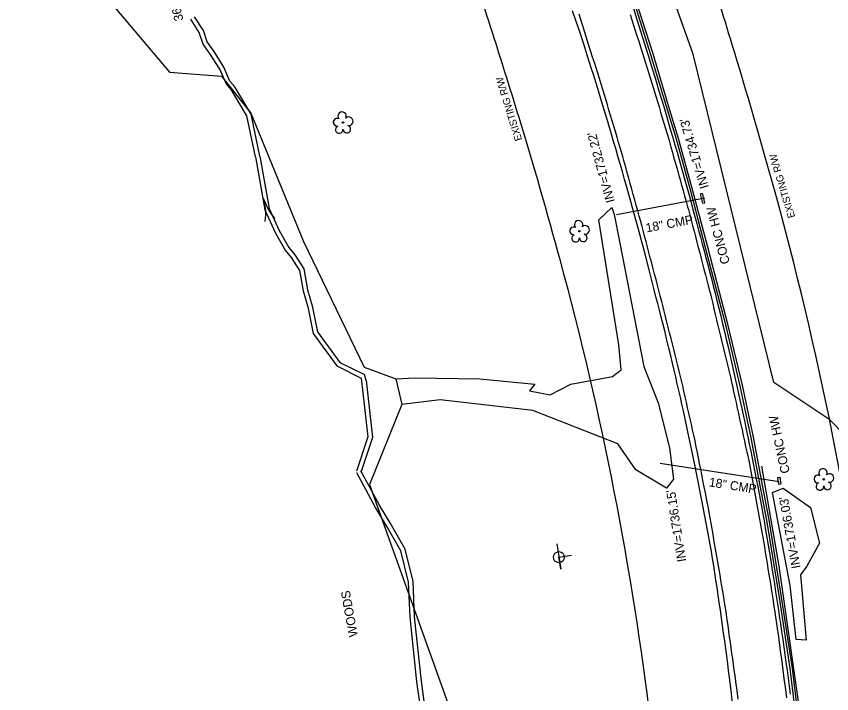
# Model space of a CAD drawing. Extents: x 472260 to 482161, y 489063 to 507124.
# Drawn here: x 481070.1 to 481432.2, y 491569.8 to 491870.7 of the extents above; entities that cross this region are included whole.
import ezdxf

# ---------------------------------------------------------------- set-up
doc = ezdxf.new("R2010")
doc.units = 0
for name, color, linetype in [('Exist Structure Minor Drop Inlet Cogo Elevation', 7, 'Continuous'), ('Exist Structure Minor Pipes CMP 15 Inch Cogo Point CELL', 7, 'Continuous'), ('Exist Structure Minor Pipes CMP 30 Inch', 7, 'Continuous'), ('Prop Drainage Structure Catch Basin Convert From Junction Box Label', 7, 'Continuous'), ('Prop Drainage Structure Drop Inlet Grate 2 Narrow Slots and Sag Grates 840 24 CELL', 7, 'Continuous'), ('Prop Drainage Structure Drop Inlet Grate 2 Wide Slots and Flat Grates 840 20 Label', 7, 'Continuous'), ('Prop Drainage Structure Pipe RCP 24in Class III', 7, 'Continuous'), ('Prop Drainage Structure Pipe RCP 36in Class III', 7, 'Continuous'), ('Prop Drainage Structure Pipe RCP 66in Class III', 7, 'Continuous'), ('Prop Drainage Structure Pipe RCP 66in Class IV', 7, 'Continuous'), ('Prop Drainage Structure Pipe RCP 66in Class IV Label', 7, 'Continuous'), ('Prop Drainage Structure Pipe Stub Out CELL', 7, 'Continuous'), ('Prop Drainage Structure Pipe Welded Steel 72in Label', 7, 'Continuous'), ('Prop Drainage Structure Plot Symbol 50 Scale', 7, 'Continuous'), ('Prop Drainage Structure Plot Symbol 50 Scale CELL', 7, 'Continuous'), ('Prop Drainage Structure Tops and Inverts LABEL', 7, 'Continuous'), ('Prop Earthen Structure Base Ditch Lateral Detail Label', 7, 'Continuous'), ('Prop Earthen Structure Berm Ditch Detail Label', 7, 'Continuous'), ('Prop Erosion Rip Rap Pad at Outlet Label', 7, 'Continuous'), ('Scratch_Level_8', 7, 'Continuous')]:
    doc.layers.add(name, color=color, linetype=linetype)

msp = doc.modelspace()

# ---------------------------------------------------------------- linework, layer by layer
at = {"layer": 'Exist Structure Minor Drop Inlet Cogo Elevation'}
for centre, radius, start, end in [((478607.84, 491005.76), 2907.95, 16.9803, 18.70399), ((478607.84, 491005.76), 2807.95, 16.9803, 18.70399), ((479235.25, 491197.35), 2251.94, 15.21582, 16.9803), ((479235.25, 491197.35), 2151.94, 15.21582, 16.9803), ((479919.39, 491383.43), 1542.95, 358.51314, 15.21582), ((479919.39, 491383.43), 1442.95, 358.51314, 15.21582)]:
    msp.add_arc(centre, radius, start, end, dxfattribs=at)
at = {"layer": 'Prop Drainage Structure Catch Basin Convert From Junction Box Label'}
for points in [[(481359.82, 491830.99), (481352.88, 491853.99), (481346.61, 491873.75), (481340.18, 491894.14), (481334.78, 491910.5), (481328.6, 491928.45), (481326.13, 491936.08)], [(481358.87, 491830.7), (481351.92, 491853.69), (481345.65, 491873.45), (481339.23, 491893.84), (481333.84, 491910.18), (481330.28, 491921.01)], [(481424.97, 491320.54), (481425.91, 491338.82), (481426.5, 491362.33), (481426.69, 491384.49), (481426.6, 491406.8), (481426.13, 491429.47), (481425.28, 491454.33), (481424.12, 491475.15), (481422.52, 491498.91), (481420.88, 491517.39), (481418.64, 491539.01), (481416.19, 491561.27), (481413.79, 491580.97), (481409.01, 491612.6), (481403.41, 491646.87), (481401.11, 491659.21), (481396.49, 491683.55), (481391.62, 491706.62), (481385.32, 491733.12), (481376.23, 491767.96), (481369.67, 491793.01), (481363.25, 491816.12), (481358.87, 491830.7)], [(481425.97, 491320.48), (481426.91, 491338.78), (481427.5, 491362.31), (481427.69, 491384.49), (481427.6, 491406.81), (481427.13, 491429.5), (481426.28, 491454.38), (481425.11, 491475.21), (481423.52, 491498.98), (481421.87, 491517.48), (481419.63, 491539.11), (481417.18, 491561.38), (481414.78, 491581.1), (481410, 491612.75), (481404.39, 491647.04), (481402.09, 491659.4), (481397.47, 491683.75), (481392.6, 491706.84), (481386.29, 491733.36), (481377.2, 491768.21), (481370.63, 491793.27), (481364.21, 491816.4), (481359.82, 491830.99)]]:
    msp.add_lwpolyline(points, dxfattribs=at)
at = {"layer": 'Prop Drainage Structure Drop Inlet Grate 2 Narrow Slots and Sag Grates 840 24 CELL'}
for points in [[(481390.63, 491567.48), (481390.33, 491569.95), (481390.03, 491572.43), (481389.73, 491574.91), (481389.68, 491575.38), (481389.33, 491577.85), (481388.99, 491580.33), (481388.64, 491582.8), (481388.3, 491585.27), (481387.95, 491587.74), (481387.61, 491590.22), (481387.26, 491592.69), (481386.92, 491595.16), (481386.57, 491597.63), (481386.23, 491600.11), (481385.88, 491602.58), (481385.54, 491605.05), (481385.49, 491605.37), (481385.08, 491607.83), (481384.68, 491610.29), (481384.27, 491612.76), (481383.86, 491615.22), (481383.45, 491617.68), (481383.04, 491620.15), (481382.64, 491622.61), (481382.23, 491625.07), (481381.82, 491627.54), (481381.41, 491630), (481381.28, 491630.8), (481380.84, 491633.26), (481380.4, 491635.72), (481379.96, 491638.18), (481379.53, 491640.64), (481379.09, 491643.09), (481378.65, 491645.55), (481378.21, 491648.01), (481377.77, 491650.47), (481377.33, 491652.93), (481376.98, 491654.94), (481376.49, 491657.39), (481376, 491659.84), (481375.52, 491662.29), (481375.03, 491664.74), (481374.54, 491667.19), (481374.06, 491669.64), (481373.57, 491672.09), (481373.09, 491674.54), (481372.6, 491676.99), (481372.11, 491679.44), (481371.63, 491681.89), (481371.56, 491682.22), (481371.01, 491684.66), (481370.46, 491687.1), (481369.91, 491689.53), (481369.36, 491691.97), (481368.81, 491694.41), (481368.26, 491696.85), (481367.71, 491699.28), (481367.16, 491701.72), (481366.61, 491704.16), (481366.06, 491706.6), (481365.51, 491709.03), (481365.14, 491710.71), (481364.53, 491713.13), (481363.92, 491715.55), (481363.31, 491717.98), (481362.7, 491720.4), (481362.09, 491722.82), (481361.48, 491725.25), (481360.88, 491727.67), (481360.27, 491730.09), (481359.66, 491732.52), (481359.05, 491734.94), (481358.44, 491737.36), (481357.83, 491739.79), (481357.22, 491742.21), (481356.74, 491744.12), (481356.11, 491746.54), (481355.48, 491748.96), (481354.84, 491751.37), (481354.21, 491753.79), (481353.58, 491756.21), (481352.94, 491758.62), (481352.31, 491761.04), (481351.68, 491763.46), (481351.04, 491765.88), (481350.41, 491768.29), (481349.77, 491770.71), (481349.14, 491773.13), (481348.51, 491775.54), (481347.87, 491777.96), (481347.45, 491779.57), (481346.78, 491781.98), (481346.12, 491784.39), (481345.45, 491786.79), (481344.78, 491789.2), (481344.11, 491791.61), (481343.44, 491794.02), (481342.77, 491796.43), (481342.1, 491798.83), (481341.44, 491801.24), (481340.77, 491803.65), (481340.1, 491806.06), (481339.43, 491808.47), (481339.03, 491809.91), (481338.32, 491812.31), (481337.6, 491814.7), (481336.89, 491817.1), (481336.17, 491819.49), (481335.46, 491821.89), (481334.75, 491824.28), (481334.03, 491826.68), (481333.32, 491829.07), (481332.61, 491831.47), (481331.89, 491833.86), (481331.18, 491836.26), (481330.58, 491838.28), (481329.82, 491840.66), (481329.07, 491843.05), (481328.32, 491845.43), (481327.57, 491847.81), (481326.82, 491850.2), (481326.07, 491852.58), (481325.32, 491854.96), (481324.56, 491857.35), (481323.81, 491859.73), (481323.06, 491862.11), (481322.31, 491864.5), (481321.56, 491866.88), (481320.81, 491869.27), (481320.06, 491871.65)], [(481342.74, 491871.53), (481343.49, 491869.15), (481344.25, 491866.77), (481345, 491864.38), (481345.76, 491862), (481346.51, 491859.62), (481347.26, 491857.24), (481348.02, 491854.86), (481348.77, 491852.47), (481349.53, 491850.09), (481350.28, 491847.71), (481351.03, 491845.33), (481351.79, 491842.94), (481352.54, 491840.56), (481352.7, 491840.07), (481353.41, 491837.67), (481354.13, 491835.28), (481354.84, 491832.88), (481355.55, 491830.49), (481356.27, 491828.09), (481356.98, 491825.7), (481357.69, 491823.3), (481358.41, 491820.91), (481359.12, 491818.51), (481359.84, 491816.12), (481360.17, 491815.01), (481360.84, 491812.6), (481361.51, 491810.19), (481362.19, 491807.79), (481362.86, 491805.38), (481363.54, 491802.98), (481364.21, 491800.57), (481364.88, 491798.16), (481365.56, 491795.76), (481366.23, 491793.35), (481366.9, 491790.94), (481367.58, 491788.54), (481368.25, 491786.13), (481368.58, 491784.95), (481369.21, 491782.53), (481369.84, 491780.11), (481370.47, 491777.69), (481371.1, 491775.28), (481371.73, 491772.86), (481372.36, 491770.44), (481372.99, 491768.02), (481373.62, 491765.6), (481374.25, 491763.19), (481374.88, 491760.77), (481375.51, 491758.35), (481376.14, 491755.93), (481376.77, 491753.52), (481377.4, 491751.1), (481378.03, 491748.68), (481378.2, 491748.03), (481378.79, 491745.6), (481379.38, 491743.17), (481379.96, 491740.74), (481380.55, 491738.32), (481381.14, 491735.89), (481381.73, 491733.46), (481382.32, 491731.03), (481382.91, 491728.6), (481383.49, 491726.18), (481384.08, 491723.75), (481384.67, 491721.32), (481385.26, 491718.89), (481385.85, 491716.46), (481386.44, 491714.04), (481387.02, 491711.61), (481387.08, 491711.39), (481387.61, 491708.95), (481388.14, 491706.5), (481388.68, 491704.06), (481389.21, 491701.62), (481389.74, 491699.18), (481390.27, 491696.74), (481390.81, 491694.3), (481391.34, 491691.86), (481391.87, 491689.42), (481392.4, 491686.98), (481392.94, 491684.54), (481393.47, 491682.1), (481394, 491679.66), (481394.54, 491677.22), (481395.07, 491674.78), (481395.52, 491672.69), (481395.98, 491670.24), (481396.43, 491667.78), (481396.88, 491665.32), (481397.33, 491662.87), (481397.79, 491660.41), (481398.24, 491657.96), (481398.69, 491655.5), (481399.14, 491653.04), (481399.6, 491650.59), (481400.05, 491648.13), (481400.5, 491645.68), (481400.96, 491643.22), (481401.41, 491640.76), (481401.54, 491640.07), (481401.94, 491637.61), (481402.34, 491635.14), (481402.74, 491632.68), (481403.14, 491630.21), (481403.54, 491627.75), (481403.94, 491625.29), (481404.34, 491622.82), (481404.74, 491620.36), (481405.14, 491617.89), (481405.54, 491615.43), (481405.94, 491612.96), (481406.25, 491611.07), (481406.6, 491608.6), (481406.96, 491606.13), (481407.32, 491603.66), (481407.67, 491601.19), (481408.03, 491598.71), (481408.39, 491596.24), (481408.74, 491593.77), (481408.9, 491592.71), (481409.22, 491590.24), (481409.55, 491587.76), (481409.87, 491585.29), (481410.2, 491582.81), (481410.52, 491580.34), (481410.85, 491577.86), (481411.17, 491575.38), (481411.5, 491572.91), (481411.82, 491570.43), (481412.15, 491567.96)]]:
    msp.add_lwpolyline(points, dxfattribs=at)
at = {"layer": 'Prop Drainage Structure Drop Inlet Grate 2 Wide Slots and Flat Grates 840 20 Label'}
for p, q in [((481215.2, 491823.54), (481215.2, 491823.54)), ((481320.21, 491775.27), (481320.21, 491775.27)), ((481428.72, 491665.06), (481428.72, 491665.06))]:
    msp.add_line(p, q, dxfattribs=at)
for centre in [(481215.2, 491823.54), (481320.21, 491775.27), (481428.72, 491665.06)]:
    msp.add_circle(centre, 0.326, dxfattribs=at)
for centre, radius, start, end in [((481214.81, 491826.42), 1.86, 330.1651, 219.7134), ((481217.75, 491824.13), 1.9, 257.1011, 134.1999), ((481212.59, 491823.7), 1.73, 62.6636, 279.3457), ((481216.87, 491820.64), 1.7, 181.2822, 74.56), ((481213.49, 491820.42), 1.69, 111.5671, 6.231), ((481319.83, 491778.15), 1.86, 330.1651, 219.7134), ((481317.61, 491775.43), 1.73, 62.6636, 279.3457), ((481322.76, 491775.86), 1.9, 257.1011, 134.1999), ((481318.51, 491772.15), 1.69, 111.5671, 6.231), ((481321.89, 491772.37), 1.7, 181.2822, 74.56), ((481426.11, 491665.21), 1.73, 62.6636, 279.3457), ((481428.33, 491667.93), 1.86, 330.1651, 219.7134), ((481431.27, 491665.65), 1.9, 257.1011, 134.1999), ((481427.01, 491661.94), 1.69, 111.5671, 6.231), ((481430.39, 491662.16), 1.7, 181.2822, 74.56)]:
    msp.add_arc(centre, radius, start, end, dxfattribs=at)
at = {"layer": 'Prop Drainage Structure Pipe RCP 24in Class III'}
for p, q in [((481212.46, 491715.45), (481223.29, 491710.04)), ((481213.79, 491717.02), (481224.68, 491711.58)), ((481225.43, 491708.94), (481224.68, 491711.58))]:
    msp.add_line(p, q, dxfattribs=at)
for points in [[(481176.35, 491808.26), (481172.48, 491826.59), (481165.49, 491838.17), (481163.24, 491840.86), (481160.47, 491847.22), (481156.24, 491853.92), (481153.03, 491858.42), (481151.36, 491863.54), (481147.6, 491869.39)], [(481178.31, 491808.67), (481174.37, 491827.33), (481167.12, 491839.34), (481164.96, 491841.92), (481162.24, 491848.16), (481157.9, 491855.04), (481154.84, 491859.34), (481153.18, 491864.41), (481149.28, 491870.47)], [(481176.35, 491808.29), (481180.41, 491784.75), (481184.99, 491774.74), (481189.43, 491766.84), (481192.13, 491763.54), (481195.87, 491757.87), (481197.53, 491748.77), (481199.54, 491741.62), (481201.99, 491729.8), (481212.46, 491715.45)], [(481178.32, 491808.63), (481182.33, 491785.35), (481186.77, 491775.64), (481191.09, 491767.97), (481193.75, 491764.72), (481197.76, 491758.63), (481199.49, 491749.22), (481201.48, 491742.09), (481203.86, 491730.63), (481213.79, 491717.02)], [(481223.29, 491710.04), (481226.22, 491683.87), (481221.25, 491668.69)], [(481225.43, 491708.94), (481228.25, 491683.67), (481223.15, 491668.07)], [(481320.59, 491449.33), (481313.1, 491462.8), (481304.83, 491471.51), (481295.35, 491480.16), (481281.8, 491500.39), (481269.7, 491514.32), (481264.62, 491522.63), (481260.04, 491532.56), (481255.9, 491543.47), (481254.81, 491551.65), (481249.6, 491563.83), (481248.04, 491575.13), (481244.97, 491603.83), (481244.34, 491619.36), (481240.86, 491633.3), (481234.54, 491644.47), (481229.69, 491652.56), (481221.32, 491667.9)], [(481322.34, 491450.3), (481314.72, 491464), (481306.23, 491472.94), (481296.87, 491481.47), (481283.39, 491501.61), (481271.32, 491515.51), (481266.39, 491523.58), (481261.88, 491533.34), (481257.86, 491543.97), (481256.76, 491552.18), (481251.54, 491564.37), (481250.02, 491575.37), (481246.97, 491603.98), (481246.33, 491619.64), (481242.73, 491634.04), (481236.27, 491645.48), (481231.42, 491653.55), (481223.08, 491668.86)]]:
    msp.add_lwpolyline(points, dxfattribs=at)
at = {"layer": 'Prop Drainage Structure Pipe RCP 36in Class III'}
for p, q in [((481375.02, 491787.7), (481373.98, 491791.94)), ((481375.83, 491787.9), (481374.79, 491792.14)), ((481408.18, 491665.82), (481408.6, 491662.91)), ((481409.17, 491665.96), (481409.59, 491663.05))]:
    msp.add_line(p, q, dxfattribs=at)
at = {"layer": 'Prop Drainage Structure Pipe RCP 66in Class IV'}
for p, q in [((481336.68, 491782.76), (481375.88, 491790.06)), ((481356.03, 491672.3), (481408.88, 491664.09))]:
    msp.add_line(p, q, dxfattribs=at)
at = {"layer": 'Prop Drainage Structure Pipe Stub Out CELL'}
for points in [[(481388.24, 491565.46), (481387.56, 491571.2), (481386.85, 491577.07), (481386.47, 491580.09), (481386.07, 491583.23), (481385.64, 491586.48), (481385.19, 491589.85), (481384.73, 491593.27), (481384.25, 491596.7), (481383.78, 491600.12), (481383.29, 491603.55), (481382.81, 491606.95), (481382.32, 491610.33), (481381.83, 491613.66), (481381.34, 491616.97), (481380.84, 491620.24), (481380.34, 491623.48), (481379.83, 491626.68), (481379.31, 491629.84), (481378.78, 491633), (481378.24, 491636.15), (481377.69, 491639.31), (481377.11, 491642.48), (481376.53, 491645.64), (481375.94, 491648.76), (481375.35, 491651.85), (481374.75, 491654.91), (481374.14, 491657.95), (481373.54, 491660.99), (481372.93, 491664.03), (481372.32, 491667.07), (481371.71, 491670.07), (481370.54, 491675.82), (481369.4, 491681.33), (481368.23, 491686.91), (481367.01, 491692.63), (481366.37, 491695.55), (481365.71, 491698.51), (481365.03, 491701.51), (481364.34, 491704.53), (481363.65, 491707.55), (481362.94, 491710.57), (481362.24, 491713.59), (481361.51, 491716.69), (481360.73, 491719.93), (481359.92, 491723.32), (481359.07, 491726.86), (481358.21, 491730.4), (481357.37, 491733.8), (481356.55, 491737.05), (481355.75, 491740.15), (481354.97, 491743.18), (481354.19, 491746.19), (481353.43, 491749.2), (481352.67, 491752.19), (481351.92, 491755.17), (481351.17, 491758.1), (481349.7, 491763.86), (481348.24, 491769.46), (481346.78, 491774.93), (481345.31, 491780.32), (481343.81, 491785.71), (481343.02, 491788.52), (481342.17, 491791.54), (481341.25, 491794.79), (481340.28, 491798.25), (481339.27, 491801.79), (481338.28, 491805.25), (481337.29, 491808.63), (481336.32, 491811.94), (481335.36, 491815.17), (481334.42, 491818.33), (481333.5, 491821.4), (481332.61, 491824.39), (481331.73, 491827.32), (481330, 491833.06), (481328.3, 491838.68), (481327.42, 491841.53), (481326.52, 491844.42), (481325.6, 491847.35), (481323.8, 491853.03), (481322.1, 491858.29), (481320.45, 491863.33), (481318.76, 491868.39), (481317.14, 491873.17)], [(481344.21, 491874.24), (481345.87, 491868.93), (481347.51, 491863.68), (481349.12, 491858.56), (481350.7, 491853.51), (481352.26, 491848.47), (481353.81, 491843.35), (481355.38, 491838.09), (481357.04, 491832.52), (481357.92, 491829.56), (481358.83, 491826.49), (481359.77, 491823.33), (481360.7, 491820.13), (481361.65, 491816.89), (481362.6, 491813.62), (481363.54, 491810.33), (481364.46, 491807.09), (481365.37, 491803.88), (481366.26, 491800.71), (481367.14, 491797.55), (481368.02, 491794.39), (481368.89, 491791.23), (481369.75, 491788.06), (481370.6, 491784.91), (481371.45, 491781.8), (481372.28, 491778.71), (481373.11, 491775.67), (481373.93, 491772.63), (481374.74, 491769.6), (481375.55, 491766.56), (481376.35, 491763.52), (481377.16, 491760.46), (481377.97, 491757.36), (481378.79, 491754.21), (481379.62, 491751.02), (481380.45, 491747.77), (481381.28, 491744.46), (481382.12, 491741.07), (481382.95, 491737.61), (481383.78, 491734.14), (481384.6, 491730.7), (481385.4, 491727.29), (481386.2, 491723.91), (481386.98, 491720.55), (481387.75, 491717.2), (481388.5, 491713.85), (481389.25, 491710.5), (481389.99, 491707.16), (481390.72, 491703.8), (481391.45, 491700.44), (481392.18, 491697.08), (481392.91, 491693.73), (481393.61, 491690.43), (481394.29, 491687.17), (481394.96, 491683.95), (481395.61, 491680.77), (481396.25, 491677.61), (481396.89, 491674.47), (481397.52, 491671.36), (481398.14, 491668.24), (481398.75, 491665.09), (481399.37, 491661.91), (481399.97, 491658.68), (481400.57, 491655.45), (481401.17, 491652.21), (481401.75, 491648.97), (481402.33, 491645.73), (481402.9, 491642.48), (481403.47, 491639.18), (481404.03, 491635.85), (481404.59, 491632.48), (481405.14, 491629.07), (481405.7, 491625.62), (481406.25, 491622.13), (481406.8, 491618.6), (481407.35, 491615.05), (481407.9, 491611.5), (481408.44, 491607.96), (481408.97, 491604.41), (481409.49, 491600.89), (481410, 491597.41), (481410.5, 491593.97), (481410.98, 491590.58), (481411.45, 491587.19), (481411.92, 491583.74), (481412.39, 491580.25), (481412.87, 491576.71), (481413.33, 491573.17), (481413.78, 491569.67)]]:
    msp.add_lwpolyline(points, dxfattribs=at)
at = {"layer": 'Prop Drainage Structure Plot Symbol 50 Scale'}
for p, q in [((481373.98, 491791.94), (481374.79, 491792.14)), ((481375.02, 491787.7), (481375.83, 491787.9)), ((481408.18, 491665.82), (481409.17, 491665.96)), ((481408.6, 491662.91), (481409.59, 491663.05))]:
    msp.add_line(p, q, dxfattribs=at)
at = {"layer": 'Prop Drainage Structure Plot Symbol 50 Scale CELL'}
msp.add_lwpolyline([(481401.12, 491670.96), (481408.83, 491626.51), (481417.64, 491564.33), (481423.77, 491502.24), (481426.23, 491466.29), (481427.33, 491437.29), (481427.85, 491395.94), (481427.63, 491358.35), (481426.51, 491320.15)], dxfattribs=at)
at = {"layer": 'Prop Drainage Structure Tops and Inverts LABEL'}
for points in [[(481238.58, 491709.7), (481247.06, 491710.08), (481276, 491709.73), (481300.45, 491707.4), (481297.95, 491704.37), (481307.24, 491702.56), (481316.33, 491707.39), (481334.94, 491710.67), (481338.78, 491713.74), (481337.71, 491724.78), (481328.76, 491780.27), (481334.62, 491785.75), (481335.58, 491782.76), (481338.18, 491769.97)], [(481338.18, 491769.97), (481348.83, 491715.15), (481355.23, 491698.98), (481360.27, 491679.06), (481361.92, 491665.2), (481358.85, 491661.17), (481345.31, 491669.25), (481337.32, 491680.83), (481299.57, 491695.68), (481258.32, 491700.33), (481241.27, 491698.34)], [(481413.83, 491617.92), (481405.93, 491659.28), (481410.67, 491661.15), (481422.87, 491652.53), (481426.8, 491636.77), (481421.2, 491626.51), (481418.37, 491622.61), (481420.97, 491593.64), (481416.41, 491593.87), (481413.83, 491617.92)]]:
    msp.add_lwpolyline(points, dxfattribs=at)
at = {"layer": 'Prop Earthen Structure Base Ditch Lateral Detail Label'}
msp.add_line((481311.05, 491630.49), (481311.05, 491630.49), dxfattribs=at)
msp.add_lwpolyline([(481310.11, 491636.35), (481311.87, 491625.15), (481311.03, 491630.48), (481316.61, 491631.38)], dxfattribs=at)
msp.add_circle((481311.06, 491630.49), 2.45, dxfattribs=at)
at = {"layer": 'Prop Erosion Rip Rap Pad at Outlet Label'}
for points in [[(481370.78, 491853.85), (481351.95, 491906.77), (481366.45, 491914.77), (481410.8, 491899.16), (481421.42, 491903.82), (481409.89, 491948.85), (481428.87, 491957.06), (481440.61, 491925.36), (481455.59, 491930.86), (481468.91, 491949.08), (481502.11, 491961.68), (481520.4, 491958.45), (481540.45, 491959.56), (481547.5, 491970.59), (481550.62, 491990.5), (481533.93, 492008.17), (481529.05, 492061.74), (481534.56, 492102.92), (481577.42, 492110.74)], [(481070.09, 491909.52), (481111.3, 491877.6), (481138.11, 491845.92), (481161.25, 491844.15), (481174.3, 491827.64)], [(481715.92, 491548.03), (481655.56, 491556.63), (481652.98, 491487.61), (481645.37, 491491.07), (481641.06, 491503.13), (481603.02, 491495.32), (481599.89, 491436.51), (481578.76, 491430.82), (481464.14, 491658.01), (481431.48, 491691.49), (481406.6, 491708.09), (481370.78, 491853.85)], [(481174.3, 491827.64), (481197.58, 491770.74), (481224.52, 491714.81), (481238.58, 491709.7), (481241.27, 491698.34), (481226.96, 491662.82), (481282.38, 491508.17), (481313.47, 491469.61), (481314.15, 491441.11), (481314.19, 491405.5), (481345.68, 491317.77)]]:
    msp.add_lwpolyline(points, dxfattribs=at)
at = {"layer": 'Scratch_Level_8'}
msp.add_line((481181.37, 491785.05), (481181.37, 491785.05), dxfattribs=at)
for points in [[(481185.02, 491780.94), (481184.05, 491782.04), (481183.2, 491783.27), (481182.36, 491784.49), (481181.65, 491785.75), (481181, 491787.08), (481180.41, 491788.45), (481179.91, 491789.83)], [(481180.65, 491779.6), (481180.83, 491781.05), (481180.85, 491782.55), (481180.86, 491784.03), (481180.74, 491785.47), (481180.54, 491786.94), (481180.26, 491788.41), (481179.91, 491789.83)]]:
    msp.add_lwpolyline(points, dxfattribs=at)

# ---------------------------------------------------------------- texts
at = {"layer": 'Exist Structure Minor Pipes CMP 15 Inch Cogo Point CELL'}
for rotation, p in [(107.1035, (481294.76, 491815.91)), (106.7371, (481416.03, 491781.67))]:
    msp.add_text('EXISTING R/W', height=3.2, rotation=rotation, dxfattribs=at).set_placement(p)
at = {"layer": 'Exist Structure Minor Pipes CMP 30 Inch'}
for rotation, p in [(104.7888, (481387.06, 491761.22)), (102.0882, (481413.66, 491668.12))]:
    msp.add_text('CONC HW', height=4, rotation=rotation, dxfattribs=at).set_placement(p)
at = {"layer": 'Prop Drainage Structure Pipe RCP 66in Class III'}
msp.add_text('WOODS', height=4, rotation=100.2978, dxfattribs=at).set_placement((481221.86, 491595.44))
at = {"layer": 'Prop Drainage Structure Pipe RCP 66in Class IV Label'}
for rotation, p in [(10.544, (481350.06, 491774.72)), (351.1699, (481377.53, 491661.98))]:
    msp.add_text('18" CMP', height=4, rotation=rotation, dxfattribs=at).set_placement(p)
at = {"layer": 'Prop Drainage Structure Pipe Welded Steel 72in Label'}
for s, rotation, p in [("INV=1734.73'", 106.6881, (481377.73, 491794.85)), ("INV=1732.22'", 105.4118, (481335.98, 491788.51)), ("INV=1736.15'", 98.9334, (481367.65, 491628.7)), ("INV=1736.03'", 100.2978, (481418.45, 491625.8))]:
    msp.add_text(s, height=4, rotation=rotation, dxfattribs=at).set_placement(p)
at = {"layer": 'Prop Earthen Structure Berm Ditch Detail Label'}
msp.add_text('36" CMP', height=4, rotation=103.3262, dxfattribs=at).set_placement((481144.34, 491869.11))

doc.saveas('drawing.dxf')
